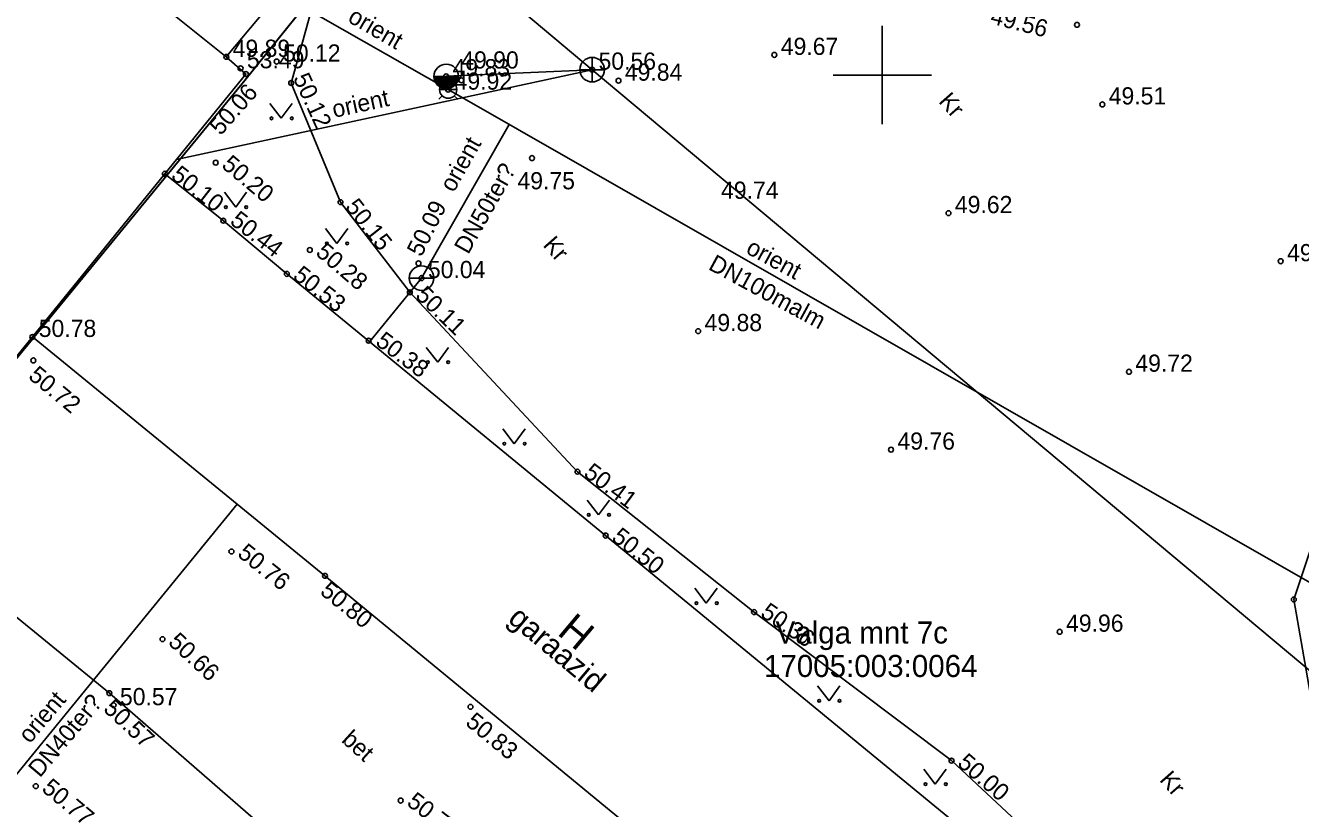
# Model space of a CAD drawing. Extents: x 640876 to 641418, y 6455595 to 6456085.
# Drawn here: x 641115.1 to 641167, y 6455820.1 to 6455852 of the extents above; entities that cross this region are included whole.
import ezdxf

# ---------------------------------------------------------------- set-up
doc = ezdxf.new("R2010")
doc.units = 0
for name, color, linetype in [('DTRASS', 7, 'Continuous'), ('HALJASTUS', 7, 'Continuous'), ('HOONE', 7, 'Continuous'), ('HOONEDET', 7, 'Continuous'), ('KKAEV', 7, 'Continuous'), ('KORGUS', 7, 'Continuous'), ('KTRASS', 7, 'Continuous'), ('MOOTKORG', 7, 'Continuous'), ('MOOTMPUNKT', 7, 'Continuous'), ('PIIR', 7, 'Continuous'), ('TEE', 7, 'Continuous'), ('VKAEV', 7, 'Continuous'), ('VORK', 7, 'Continuous'), ('VTRASS', 7, 'Continuous')]:
    doc.layers.add(name, color=color, linetype=linetype)

msp = doc.modelspace()

# ---------------------------------------------------------------- linework, layer by layer
at = {"layer": 'DTRASS'}
msp.add_line((641138.181, 6455850.219), (641132.234, 6455849.95), dxfattribs=at)
at = {"layer": 'HALJASTUS'}
for p, q in [((641125.054, 6455848.844), (641125.517, 6455848.237)), ((641125.517, 6455848.237), (641125.963, 6455848.844)), ((641123.197, 6455845.223), (641123.66, 6455844.616)), ((641123.66, 6455844.616), (641124.106, 6455845.223)), ((641127.312, 6455843.75), (641127.776, 6455843.143)), ((641127.776, 6455843.143), (641128.221, 6455843.75)), ((641131.424, 6455838.906), (641131.888, 6455838.299)), ((641131.888, 6455838.299), (641132.333, 6455838.906)), ((641134.542, 6455835.588), (641135.005, 6455834.981)), ((641135.005, 6455834.981), (641135.451, 6455835.588)), ((641137.977, 6455832.686), (641138.441, 6455832.079)), ((641138.441, 6455832.079), (641138.886, 6455832.686)), ((641142.365, 6455829.094), (641142.828, 6455828.487)), ((641142.828, 6455828.487), (641143.274, 6455829.094)), ((641147.368, 6455825.113), (641147.831, 6455824.506)), ((641147.831, 6455824.506), (641148.277, 6455825.113)), ((641151.699, 6455821.721), (641152.162, 6455821.114)), ((641152.162, 6455821.114), (641152.608, 6455821.721))]:
    msp.add_line(p, q, dxfattribs=at)
for centre in [(641125.116, 6455848.237), (641125.945, 6455848.237), (641123.259, 6455844.616), (641124.088, 6455844.616), (641127.375, 6455843.143), (641128.204, 6455843.143), (641131.487, 6455838.299), (641132.316, 6455838.299), (641134.604, 6455834.981), (641135.433, 6455834.981), (641138.04, 6455832.079), (641138.868, 6455832.079), (641142.427, 6455828.487), (641143.256, 6455828.487), (641147.43, 6455824.506), (641148.259, 6455824.506), (641151.761, 6455821.114), (641152.59, 6455821.114)]:
    msp.add_circle(centre, 0.055, dxfattribs=at)
at = {"layer": 'HOONE'}
msp.add_lwpolyline([(641139.149, 6455869.673), (641123.276, 6455850.742), (641124.076, 6455850.041), (641120.776, 6455845.978), (641123.157, 6455844.065), (641125.741, 6455841.899), (641129.074, 6455839.178), (641138.729, 6455831.239), (641154.511, 6455818.271), (641155.863, 6455817.162), (641166.356, 6455808.477), (641157.088, 6455797.138), (641158.337, 6455796.148), (641152.522, 6455789.036), (641139.095, 6455799.993), (641148.747, 6455811.989), (641140.492, 6455818.73), (641127.295, 6455829.597), (641115.375, 6455839.33), (641112.285, 6455835.53)], dxfattribs=at)
at = {"layer": 'HOONEDET'}
for p, q in [((641085.613, 6455880.964), (641123.276, 6455850.742)), ((641120.776, 6455845.978), (641115.375, 6455839.33))]:
    msp.add_line(p, q, dxfattribs=at)
at = {"layer": 'KKAEV'}
for p, q in [((641138.181, 6455849.719), (641138.181, 6455850.719)), ((641137.681, 6455850.219), (641138.681, 6455850.219))]:
    msp.add_line(p, q, dxfattribs=at)
msp.add_circle((641138.181, 6455850.219), 0.5, dxfattribs=at)
at = {"layer": 'KORGUS'}
for centre in [(641145.606, 6455850.821), (641124.076, 6455850.041), (641125.918, 6455849.675), (641132.854, 6455849.785), (641139.253, 6455849.77), (641158.966, 6455848.803), (641122.845, 6455846.432), (641135.731, 6455846.616), (641120.776, 6455845.978), (641127.928, 6455844.823), (641152.699, 6455844.375), (641123.157, 6455844.065), (641126.678, 6455842.873), (641131.107, 6455842.327), (641166.233, 6455842.415), (641125.741, 6455841.899), (641130.752, 6455841.149), (641142.502, 6455839.567), (641129.074, 6455839.178), (641115.417, 6455838.374), (641160.051, 6455837.913), (641150.359, 6455834.74), (641137.584, 6455833.839), (641138.729, 6455831.239), (641123.486, 6455830.59), (641127.295, 6455829.597), (641144.779, 6455828.121), (641120.679, 6455827.018), (641157.228, 6455827.32), (641118.513, 6455824.816), (641133.225, 6455824.26), (641152.823, 6455822.069), (641115.514, 6455821.03), (641130.379, 6455820.442)]:
    msp.add_circle(centre, 0.1, dxfattribs=at)
at = {"layer": 'KTRASS'}
for p, q in [((641138.181, 6455850.219), (641129.171, 6455857.773)), ((641138.181, 6455850.219), (641121.249, 6455846.561)), ((641169.258, 6455824.192), (641138.181, 6455850.219))]:
    msp.add_line(p, q, dxfattribs=at)
at = {"layer": 'MOOTMPUNKT'}
for centre in [(641157.935, 6455852.048), (641123.276, 6455850.742), (641125.328, 6455850.549), (641123.857, 6455850.276), (641132.234, 6455849.95), (641138.181, 6455850.219), (641132.318, 6455849.405), (641131.23, 6455841.728), (641115.375, 6455839.33), (641166.769, 6455828.637), (641118.683, 6455824.328)]:
    msp.add_circle(centre, 0.1, dxfattribs=at)
at = {"layer": 'PIIR'}
for points in [[(641098.62, 6455818.85), (641093.41, 6455823.22), (641084.65, 6455830.08), (641067.32, 6455843.61), (641055.55, 6455852.8), (641061.31, 6455859.9), (641051.68, 6455867.61), (641067, 6455888.54), (641060.97, 6455894.57), (641075.14, 6455914.24), (641087.11, 6455930.82), (641102.26, 6455951.82), (641160.91, 6455891.99), (641157.02, 6455885.66), (641139.49, 6455869), (641124.05, 6455849.81)], [(641216.67, 6455752.61), (641192, 6455776.86), (641152.58, 6455788.91), (641136.9, 6455789.33), (641119.28, 6455802.72), (641101.72, 6455816.27), (641098.61, 6455818.83), (641124.03, 6455849.78), (641139.51, 6455868.99), (641157, 6455885.69), (641191.84, 6455860.59), (641168.46, 6455829.03), (641191.37, 6455806.79), (641234.69, 6455771.62)]]:
    msp.add_lwpolyline(points, close=True, dxfattribs=at)
at = {"layer": 'TEE'}
for points in [[(641159.238, 6455874.204), (641158.276, 6455874.888), (641154.5, 6455876.457), (641151.524, 6455876.394), (641148.985, 6455874.775), (641145.506, 6455872.238), (641137.229, 6455865.803), (641131.822, 6455858.971), (641127.09, 6455853.908), (641125.918, 6455849.675), (641127.928, 6455844.823), (641130.752, 6455841.149), (641137.584, 6455833.839), (641144.779, 6455828.121), (641152.823, 6455822.069), (641161.624, 6455813.864), (641167.235, 6455809.577)], [(641180.696, 6455804.462), (641172.269, 6455816.081), (641168.21, 6455822.681), (641167.472, 6455824.588), (641166.769, 6455828.637), (641167.7, 6455831.443), (641172.464, 6455837.156), (641175.489, 6455842.795)], [(641138.34, 6455800.592), (641134.265, 6455803.889), (641135.895, 6455805.73), (641133.001, 6455808.025), (641131.761, 6455809.021), (641133.931, 6455811.803), (641128.658, 6455815.989), (641118.513, 6455824.816), (641109.861, 6455831.873)]]:
    msp.add_lwpolyline(points, dxfattribs=at)
at = {"layer": 'VKAEV'}
for p, q in [((641131.736, 6455849.947), (641132.736, 6455849.947)), ((641132.071, 6455849.158), (641131.931, 6455849.018)), ((641131.968, 6455849.405), (641132.668, 6455849.405)), ((641132.565, 6455849.158), (641132.705, 6455849.018)), ((641130.73, 6455841.728), (641131.73, 6455841.728))]:
    msp.add_line(p, q, dxfattribs=at)
for centre, radius in [((641132.318, 6455849.405), 0.35), ((641131.23, 6455841.728), 0.5)]:
    msp.add_circle(centre, radius, dxfattribs=at)
for radius, start, end in [(0.5, 359.9987, 179.9718), (0.5, 180, 0), (0.475, 180, 0), (0.45, 180, 0), (0.425, 180, 0), (0.4, 180, 0), (0.375, 180, 0), (0.35, 180, 0), (0.325, 180, 0), (0.3, 180, 0), (0.275, 180, 0), (0.25, 180, 0), (0.225, 180, 0), (0.2, 180, 0), (0.175, 180, 0), (0.15, 180, 0), (0.125, 180, 0), (0.1, 180, 0), (0.075, 180, 0), (0.05, 180, 0), (0.025, 180, 0)]:
    msp.add_arc((641132.236, 6455849.947), radius, start, end, dxfattribs=at)
at = {"layer": 'VORK'}
for p, q in [((641150, 6455852), (641150, 6455848)), ((641148, 6455850), (641152, 6455850))]:
    msp.add_line(p, q, dxfattribs=at)
at = {"layer": 'VTRASS'}
for p, q in [((641132.02, 6455849.576), (641132.234, 6455849.95)), ((641131.23, 6455841.728), (641134.807, 6455847.981)), ((641129.118, 6455839.142), (641131.23, 6455841.728))]:
    msp.add_line(p, q, dxfattribs=at)
for points in [[(641125.449, 6455853.334), (641132.318, 6455849.405), (641171.673, 6455826.892)], [(641123.713, 6455832.522), (641112.411, 6455818.681), (641151.409, 6455786.838)]]:
    msp.add_lwpolyline(points, dxfattribs=at)

# ---------------------------------------------------------------- texts
at = {"layer": 'HOONE'}
for s, height, p in [('garaazid', 0.9, (641134.704, 6455827.761)), ('H', 1.2, (641136.715, 6455827.237))]:
    msp.add_text(s, height=height, rotation=320.0136, dxfattribs=at).set_placement(p)
at = {"layer": 'KORGUS'}
for s, rotation, p in [(' 49.56', 345.779, (641154.115, 6455852.17)), (' 50.12', 294.5939, (641125.876, 6455850.121)), (' 50.06', 48.4593, (641122.874, 6455847.311)), (' 50.10', 322.0311, (641120.776, 6455845.978)), (' 50.20', 320.0345, (641122.845, 6455846.432)), (' 50.15', 308.2711, (641127.928, 6455844.823)), (' 50.09', 63.4211, (641131.107, 6455842.327)), (' 50.44', 322.261, (641123.178, 6455844.126)), (' 50.28', 319.4882, (641126.678, 6455842.873)), (' 50.53', 321.7676, (641125.741, 6455841.899)), (' 50.11', 316.1745, (641130.752, 6455841.149)), (' 50.38', 322.9574, (641129.105, 6455839.197)), (' 50.72', 320.2872, (641114.97, 6455837.836)), (' 50.41', 323.3571, (641137.584, 6455833.839)), (' 50.50', 321.4527, (641138.729, 6455831.239)), (' 50.76', 321.2542, (641123.486, 6455830.59)), (' 50.80', 320.8675, (641126.853, 6455829.054)), (' 50.36', 325.5346, (641144.779, 6455828.121)), (' 50.66', 317.2986, (641120.679, 6455827.018)), (' 50.57', 317.112, (641118.037, 6455824.303)), (' 50.83', 320.4711, (641132.779, 6455823.72)), (' 50.00', 319.2159, (641152.823, 6455822.069)), (' 50.77', 320.1888, (641115.514, 6455821.03)), (' 50.79', 322.5843, (641130.379, 6455820.442))]:
    msp.add_text(s, height=0.7, rotation=rotation, dxfattribs=at).set_placement(p)
for s, p in [(' 49.67', (641145.606, 6455850.821)), (' 49.90', (641132.589, 6455850.266)), (' 49.84', (641139.253, 6455849.77)), (' 49.51', (641158.966, 6455848.803)), (' 49.75', (641134.878, 6455845.346)), (' 49.62', (641152.699, 6455844.375)), (' 49.44', (641166.233, 6455842.415)), (' 49.88', (641142.502, 6455839.567)), (' 49.72', (641160.051, 6455837.913)), (' 49.76', (641150.359, 6455834.74)), (' 49.96', (641157.228, 6455827.32))]:
    msp.add_text(s, height=0.7, dxfattribs=at).set_placement(p)
at = {"layer": 'KTRASS'}
msp.add_text('orient', height=0.7, rotation=12.1916, dxfattribs=at).set_placement((641127.669, 6455848.255))
at = {"layer": 'MOOTKORG'}
for s, p in [(' 49.89', (641123.276, 6455850.742)), (' 53.49', (641123.857, 6455850.276)), (' 50.12', (641125.328, 6455850.549)), (' 49.83', (641132.234, 6455849.95)), (' 50.56', (641138.181, 6455850.219)), (' 49.92', (641132.318, 6455849.405)), (' 49.74', (641143.172, 6455844.959)), (' 50.04', (641131.23, 6455841.728)), (' 50.78', (641115.375, 6455839.33)), (' 50.57', (641118.683, 6455824.328))]:
    msp.add_text(s, height=0.7, dxfattribs=at).set_placement(p)
at = {"layer": 'PIIR'}
for s, p in [('Valga mnt 7c', (641145.652, 6455826.839)), ('17005:003:0064', (641145.18, 6455825.476))]:
    msp.add_text(s, height=0.9, dxfattribs=at).set_placement(p)
at = {"layer": 'TEE'}
for s, rotation, p in [('Kr', 311.4262, (641152.263, 6455848.909)), ('Kr', 311.4262, (641136.143, 6455843.056)), ('bet', 317.8346, (641127.934, 6455822.862)), ('Kr', 311.4262, (641161.26, 6455821.268))]:
    msp.add_text(s, height=0.7, rotation=rotation, dxfattribs=at).set_placement(p)
at = {"layer": 'VTRASS'}
for s, rotation, p in [('orient', 329.7779, (641128.182, 6455852.199)), ('orient', 60.5535, (641132.54, 6455845.183)), ('DN50ter?', 60.5535, (641133.131, 6455842.662)), ('orient', 331.4885, (641144.399, 6455842.767)), ('DN100malm', 331.4885, (641142.874, 6455842.106)), ('orient', 49.8347, (641115.273, 6455822.732)), ('DN40ter?', 49.8347, (641115.682, 6455821.345))]:
    msp.add_text(s, height=0.7, rotation=rotation, dxfattribs=at).set_placement(p)

doc.saveas('drawing.dxf')
